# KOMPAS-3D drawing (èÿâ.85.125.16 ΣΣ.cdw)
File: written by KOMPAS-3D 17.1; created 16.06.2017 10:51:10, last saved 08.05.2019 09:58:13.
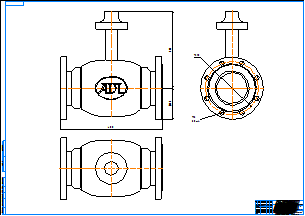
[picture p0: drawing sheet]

Sheet 1: A0, landscape

Title block, sheet 1: name: КШГ.85.125.16 фф; material: Внимание! Данный продукт является объектом авторского права ООО «Торговый Дом АДЛ». / Запрещается изменение, копирование, распространение / (в том числе путем копирования на другие сайты и ресурсы в Интернете) / или любое иное использование информации и объектов без предварительного / согласия правообладателя (ООО «Торговый Дом АДЛ»).; scale: 1:1; sheets: 1; organisation: ООО "Торговый дом АДЛ"; sheet format: A0; stored path: C:\Users\tra\Desktop\2д чертежи\Шаровые краны БИВАЛ\КШ_Бивал_серия_82_85\KOMPAS 2D\КШГ.85.125.16 фф.cdw

Views: Спереди 1, Проекционный вид 2, Проекционный вид 3
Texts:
  Klimkovich
  ADL
Dimensions and other numbers on the sheet: 400; 300; 122,5; 210; 18; 8 Отв.; 1:1; 1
